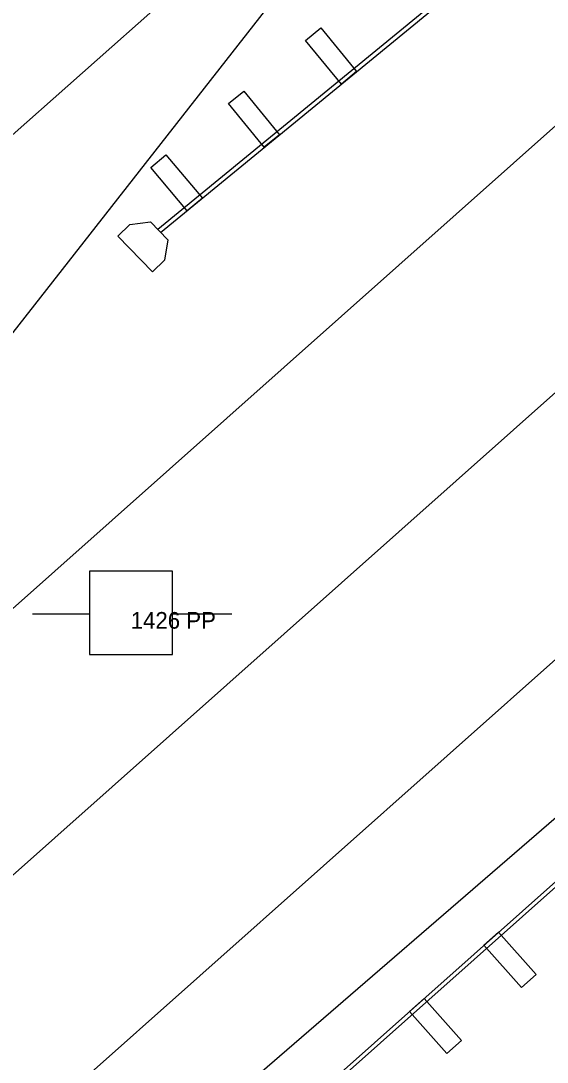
# Model space of a CAD drawing. Extents: x 49683 to 58852, y 49525 to 54803.
# Drawn here: x 55211.6 to 55243.3, y 52981.9 to 53044.6 of the extents above; entities that cross this region are included whole.
import ezdxf

# ---------------------------------------------------------------- set-up
doc = ezdxf.new("R2010")
doc.units = 0
for name, color, linetype in [('Level 11', 7, 'Continuous'), ('Level 13', 7, 'Continuous'), ('Level 19', 7, 'Continuous'), ('Level 20', 7, 'Continuous'), ('Level 27', 7, 'Continuous'), ('Level 3', 7, 'Continuous'), ('Level 59', 7, 'Continuous'), ('Level 8', 7, 'Continuous'), ('Level 9', 7, 'Continuous')]:
    doc.layers.add(name, color=color, linetype=linetype)

# ---------------------------------------------------------------- blocks, each defined once
blk = doc.blocks.new('PP')
at = {"layer": 'Level 9'}
for p, q in [((2.526, 2.452), (-2.474, 2.452)), ((-2.474, 2.452), (-2.474, -2.548)), ((2.526, -2.548), (2.526, 2.452)), ((-5.905, -0.111), (-2.436, -0.111)), ((2.454, -0.111), (6.095, -0.111)), ((-2.474, -2.548), (2.526, -2.548))]:
    blk.add_line(p, q, dxfattribs=at)

msp = doc.modelspace()

# ---------------------------------------------------------------- linework, layer by layer
at = {"layer": 'Level 11'}
msp.add_line((55223.521, 52979.087), (55416.975, 53146.156), dxfattribs=at)
at = {"layer": 'Level 13'}
msp.add_line((55279.532, 53069.998), (53969.027, 51905.114), dxfattribs=at)
at = {"layer": 'Level 19'}
msp.add_line((54181.768, 52078.16), (56150.851, 53828.445), dxfattribs=at)
at = {"layer": 'Level 20'}
for p, q in [((54173.795, 52087.129), (55269.449, 53061.037)), ((54189.74, 52069.191), (55278.865, 53037.296))]:
    msp.add_line(p, q, dxfattribs=at)
at = {"layer": 'Level 27'}
for p, q in [((55219.876, 53032.024), (55239.225, 53047.886)), ((55220.042, 53031.837), (55239.391, 53047.699)), ((55228.771, 53043.385), (55229.683, 53044.137)), ((55229.683, 53044.137), (55231.845, 53041.513)), ((55230.933, 53040.761), (55228.771, 53043.385)), ((55231.845, 53041.513), (55230.933, 53040.761)), ((55224.137, 53039.595), (55225.053, 53040.342)), ((55225.053, 53040.342), (55227.201, 53037.706)), ((55226.285, 53036.959), (55224.137, 53039.595)), ((55227.201, 53037.706), (55226.285, 53036.959)), ((55219.463, 53035.739), (55220.367, 53036.5)), ((55220.367, 53036.5), (55222.557, 53033.899)), ((55221.653, 53033.138), (55219.463, 53035.739)), ((55222.557, 53033.899), (55221.653, 53033.138)), ((55265.996, 53012.478), (55144.542, 52904.519)), ((55144.708, 52904.332), (55266.162, 53012.291)), ((55239.51, 52988.942), (55240.394, 52989.727)), ((55240.394, 52989.727), (55242.652, 52987.186)), ((55239.51, 52988.942), (55241.769, 52986.401)), ((55241.769, 52986.401), (55239.51, 52988.942)), ((55242.652, 52987.186), (55241.769, 52986.401)), ((55235.025, 52984.957), (55235.909, 52985.742)), ((55235.909, 52985.742), (55238.167, 52983.2)), ((55235.025, 52984.957), (55237.284, 52982.415)), ((55237.284, 52982.415), (55235.025, 52984.957)), ((55238.167, 52983.2), (55237.284, 52982.415))]:
    msp.add_line(p, q, dxfattribs=at)
msp.add_lwpolyline([(55218.193, 53032.307), (55219.432, 53032.466), (55220.477, 53031.389), (55220.282, 53030.154), (55219.564, 53029.458), (55217.475, 53031.611)], close=True, dxfattribs=at)
at = {"layer": 'Level 3'}
msp.add_line((55065.24, 52908.355), (55241.707, 53064.82), dxfattribs=at)
at = {"layer": 'Level 8'}
msp.add_line((55179.239, 52985.046), (55241.707, 53064.82), dxfattribs=at)

# ---------------------------------------------------------------- block references
at = {"layer": 'Level 9'}
msp.add_blockref('PP', (55218.243, 53008.988), dxfattribs=at)

# ---------------------------------------------------------------- texts
at = {"layer": 'Level 59'}
msp.add_text('1426 PP', height=1, dxfattribs=at).set_placement((55218.243, 53007.988))

doc.saveas('drawing.dxf')
